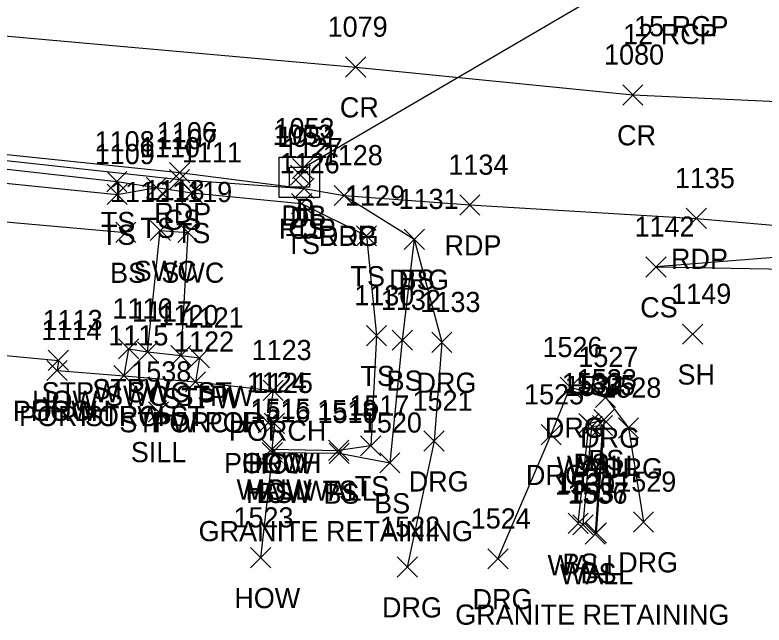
# Model space of a CAD drawing. Extents: x 1657482 to 1661439, y 647981 to 649041.
# Drawn here: x 1659731.7 to 1659806, y 648045.8 to 648106.3 of the extents above; entities that cross this region are included whole.
import ezdxf

# ---------------------------------------------------------------- set-up
doc = ezdxf.new("R2010")
doc.units = 0
for name, color, linetype in [('D_A', 7, 'Continuous'), ('D_C', 7, 'Continuous'), ('D_I', 7, 'Continuous'), ('D_TIC', 7, 'Continuous'), ('DCP', 7, 'Continuous'), ('DS', 7, 'Continuous'), ('L_A', 7, 'Continuous'), ('L_C', 7, 'Continuous'), ('L_I', 7, 'Continuous'), ('L_TIC', 7, 'Continuous'), ('LBC', 7, 'Continuous'), ('LBF', 7, 'Continuous'), ('LELB', 7, 'Continuous'), ('LW', 7, 'Continuous'), ('P_A', 7, 'Continuous'), ('P_I', 7, 'Continuous'), ('P_TIC', 7, 'Continuous'), ('PET', 7, 'Continuous'), ('PRC', 7, 'Continuous'), ('R_A', 7, 'Continuous'), ('R_I', 7, 'Continuous'), ('R_TIC', 7, 'Continuous'), ('RDG', 7, 'Continuous'), ('RSW', 7, 'Continuous')]:
    doc.layers.add(name, color=color, linetype=linetype)

msp = doc.modelspace()

# ---------------------------------------------------------------- linework, layer by layer
at = {"layer": 'D_TIC'}
for points in [[(1659759.227, 648090.081), (1659761.227, 648092.081)], [(1659761.227, 648090.081), (1659759.227, 648092.081)], [(1659759.037, 648089.421), (1659761.037, 648091.421)], [(1659761.037, 648089.421), (1659759.037, 648091.421)]]:
    msp.add_lwpolyline(points, dxfattribs=at)
at = {"layer": 'DCP'}
msp.add_lwpolyline([(1659796.66, 648112.405), (1659760.227, 648091.081)], dxfattribs=at)
at = {"layer": 'DS'}
for p, q in [((1659757.931, 648092.219), (1659761.931, 648092.219)), ((1659757.931, 648088.219), (1659757.931, 648092.219)), ((1659761.931, 648092.219), (1659761.931, 648088.219)), ((1659758.931, 648089.219), (1659758.931, 648091.219)), ((1659758.931, 648091.219), (1659760.931, 648091.219)), ((1659760.931, 648091.219), (1659760.931, 648089.219)), ((1659759.936, 648090.221), (1659759.936, 648090.221)), ((1659759.936, 648090.221), (1659759.936, 648090.221)), ((1659760.931, 648089.219), (1659758.931, 648089.219)), ((1659761.931, 648088.219), (1659757.931, 648088.219))]:
    msp.add_line(p, q, dxfattribs=at)
at = {"layer": 'L_TIC'}
for points in [[(1659747.036, 648088.997), (1659749.036, 648090.997)], [(1659749.036, 648088.997), (1659747.036, 648090.997)], [(1659740.823, 648088.778), (1659742.823, 648090.778)], [(1659742.823, 648088.778), (1659740.823, 648090.778)], [(1659740.847, 648087.516), (1659742.847, 648089.516)], [(1659742.847, 648087.516), (1659740.847, 648089.516)], [(1659744.757, 648088.198), (1659746.757, 648090.198)], [(1659746.757, 648088.198), (1659744.757, 648090.198)], [(1659744.757, 648088.198), (1659746.757, 648090.198)], [(1659746.757, 648088.198), (1659744.757, 648090.198)], [(1659748.269, 648087.683), (1659750.269, 648089.683)], [(1659750.269, 648087.683), (1659748.269, 648089.683)], [(1659759.398, 648088.114), (1659761.398, 648090.114)], [(1659761.398, 648088.114), (1659759.398, 648090.114)], [(1659759.143, 648086.603), (1659761.143, 648088.603)], [(1659761.143, 648086.603), (1659759.143, 648088.603)], [(1659741.71, 648083.749), (1659743.71, 648085.749)], [(1659743.71, 648083.749), (1659741.71, 648085.749)], [(1659765.578, 648083.403), (1659767.578, 648085.403)], [(1659767.578, 648083.403), (1659765.578, 648085.403)], [(1659770.317, 648083.067), (1659772.317, 648085.067)], [(1659772.317, 648083.067), (1659770.317, 648085.067)], [(1659794.275, 648080.325), (1659796.275, 648082.325)], [(1659796.275, 648080.325), (1659794.275, 648082.325)], [(1659766.572, 648073.522), (1659768.572, 648075.522)], [(1659768.572, 648073.522), (1659766.572, 648075.522)], [(1659797.923, 648073.665), (1659799.923, 648075.665)], [(1659799.923, 648073.665), (1659797.923, 648075.665)], [(1659769.125, 648073.06), (1659771.125, 648075.06)], [(1659771.125, 648073.06), (1659769.125, 648075.06)], [(1659741.995, 648072.212), (1659743.995, 648074.212)], [(1659743.995, 648072.212), (1659741.995, 648074.212)], [(1659743.871, 648071.903), (1659745.871, 648073.903)], [(1659745.871, 648071.903), (1659743.871, 648073.903)], [(1659747.168, 648071.552), (1659749.168, 648073.552)], [(1659749.168, 648071.552), (1659747.168, 648073.552)], [(1659749.005, 648071.317), (1659751.005, 648073.317)], [(1659751.005, 648071.317), (1659749.005, 648073.317)], [(1659735.024, 648071.064), (1659737.024, 648073.064)], [(1659737.024, 648071.064), (1659735.024, 648073.064)], [(1659734.891, 648070.068), (1659736.891, 648072.068)], [(1659736.891, 648070.068), (1659734.891, 648072.068)], [(1659734.891, 648070.068), (1659736.891, 648072.068)], [(1659736.891, 648070.068), (1659734.891, 648072.068)], [(1659741.54, 648069.547), (1659743.54, 648071.547)], [(1659743.54, 648069.547), (1659741.54, 648071.547)], [(1659741.54, 648069.547), (1659743.54, 648071.547)], [(1659743.54, 648069.547), (1659741.54, 648071.547)], [(1659748.618, 648068.931), (1659750.618, 648070.931)], [(1659750.618, 648068.931), (1659748.618, 648070.931)], [(1659748.618, 648068.931), (1659750.618, 648070.931)], [(1659750.618, 648068.931), (1659748.618, 648070.931)], [(1659756.314, 648068.091), (1659758.314, 648070.091)], [(1659758.314, 648068.091), (1659756.314, 648070.091)], [(1659744.948, 648065.971), (1659746.948, 648067.971)], [(1659746.948, 648065.971), (1659744.948, 648067.971)], [(1659755.822, 648064.888), (1659757.822, 648066.888)], [(1659757.822, 648064.888), (1659755.822, 648066.888)], [(1659755.822, 648064.888), (1659757.822, 648066.888)], [(1659757.822, 648064.888), (1659755.822, 648066.888)], [(1659756.441, 648064.828), (1659758.441, 648066.828)], [(1659758.441, 648064.828), (1659756.441, 648066.828)], [(1659787.642, 648064.811), (1659789.642, 648066.811)], [(1659789.642, 648064.811), (1659787.642, 648066.811)], [(1659787.932, 648064.531), (1659789.932, 648066.531)], [(1659789.932, 648064.531), (1659787.932, 648066.531)], [(1659788.977, 648064.607), (1659790.977, 648066.607)], [(1659790.977, 648064.607), (1659788.977, 648066.607)], [(1659789.124, 648065.193), (1659791.124, 648067.193)], [(1659791.124, 648065.193), (1659789.124, 648067.193)], [(1659756.202, 648062.257), (1659758.202, 648064.257)], [(1659758.202, 648062.257), (1659756.202, 648064.257)], [(1659756.202, 648062.257), (1659758.202, 648064.257)], [(1659758.202, 648062.257), (1659756.202, 648064.257)], [(1659765.992, 648062.591), (1659767.992, 648064.591)], [(1659767.992, 648062.591), (1659765.992, 648064.591)], [(1659756.239, 648061.928), (1659758.239, 648063.928)], [(1659758.239, 648061.928), (1659756.239, 648063.928)], [(1659756.239, 648061.928), (1659758.239, 648063.928)], [(1659758.239, 648061.928), (1659756.239, 648063.928)], [(1659762.81, 648062.143), (1659764.81, 648064.143)], [(1659764.81, 648062.143), (1659762.81, 648064.143)], [(1659762.81, 648062.143), (1659764.81, 648064.143)], [(1659764.81, 648062.143), (1659762.81, 648064.143)], [(1659762.867, 648061.857), (1659764.867, 648063.857)], [(1659764.867, 648061.857), (1659762.867, 648063.857)], [(1659767.897, 648060.904), (1659769.897, 648062.904)], [(1659769.897, 648060.904), (1659767.897, 648062.904)], [(1659767.897, 648060.904), (1659769.897, 648062.904)], [(1659769.897, 648060.904), (1659767.897, 648062.904)], [(1659786.559, 648054.92), (1659788.559, 648056.92)], [(1659788.559, 648054.92), (1659786.559, 648056.92)], [(1659787.047, 648054.764), (1659789.047, 648056.764)], [(1659789.047, 648054.764), (1659787.047, 648056.764)], [(1659788.253, 648053.862), (1659790.253, 648055.862)], [(1659790.253, 648053.862), (1659788.253, 648055.862)], [(1659788.356, 648053.962), (1659790.356, 648055.962)], [(1659790.356, 648053.962), (1659788.356, 648055.962)], [(1659755.082, 648051.504), (1659757.082, 648053.504)], [(1659757.082, 648051.504), (1659755.082, 648053.504)]]:
    msp.add_lwpolyline(points, dxfattribs=at)
at = {"layer": 'LBC'}
for points in [[(1659711.492, 648074.514), (1659713.585, 648074.237), (1659720.336, 648073.554), (1659736.024, 648072.064), (1659735.891, 648071.068)], [(1659756.822, 648065.888), (1659757.441, 648065.828), (1659757.202, 648063.257), (1659757.239, 648062.928), (1659756.082, 648052.504)]]:
    msp.add_lwpolyline(points, dxfattribs=at)
at = {"layer": 'LBF'}
for points in [[(1659742.54, 648070.547), (1659742.995, 648073.212), (1659744.871, 648072.903), (1659748.168, 648072.552), (1659750.005, 648072.317), (1659749.618, 648069.931)], [(1659735.891, 648071.068), (1659742.54, 648070.547), (1659749.618, 648069.931), (1659757.314, 648069.091), (1659756.822, 648065.888)]]:
    msp.add_lwpolyline(points, dxfattribs=at)
at = {"layer": 'LELB'}
for points in [[(1659698.339, 648094.515), (1659720.268, 648093.031), (1659748.036, 648089.997), (1659760.398, 648089.114)], [(1659698.344, 648093.996), (1659720.032, 648092.239), (1659741.823, 648089.778), (1659745.757, 648089.198), (1659749.269, 648088.683), (1659760.143, 648087.603), (1659766.578, 648084.403), (1659767.572, 648074.522), (1659766.992, 648063.591), (1659763.81, 648063.143)], [(1659701.625, 648092.494), (1659719.726, 648090.762), (1659741.847, 648088.516), (1659745.757, 648089.198)], [(1659719.21, 648086.816), (1659742.71, 648084.749)], [(1659771.317, 648084.067), (1659770.125, 648074.06), (1659768.897, 648061.904)], [(1659855.388, 648078.995), (1659852.388, 648081.027), (1659841.119, 648082.553), (1659821.287, 648083.368), (1659795.275, 648081.325), (1659823.275, 648080.854), (1659837.829, 648081.022), (1659847.593, 648080.286), (1659853.195, 648078.545)], [(1659787.559, 648055.92), (1659788.642, 648065.811), (1659790.124, 648066.193), (1659789.356, 648054.962)], [(1659757.239, 648062.928), (1659763.867, 648062.857), (1659768.897, 648061.904)]]:
    msp.add_lwpolyline(points, dxfattribs=at)
at = {"layer": 'LW'}
for points in [[(1659788.047, 648055.764), (1659788.932, 648065.531), (1659789.977, 648065.607), (1659789.253, 648054.862)], [(1659757.202, 648063.257), (1659763.81, 648063.143)]]:
    msp.add_lwpolyline(points, dxfattribs=at)
at = {"layer": 'P_TIC'}
for points in [[(1659764.503, 648100.141), (1659766.503, 648102.141)], [(1659766.503, 648100.141), (1659764.503, 648102.141)], [(1659791.988, 648097.376), (1659793.988, 648099.376)], [(1659793.988, 648097.376), (1659791.988, 648099.376)], [(1659747.043, 648089.675), (1659749.043, 648091.675)], [(1659749.043, 648089.675), (1659747.043, 648091.675)], [(1659759.398, 648088.114), (1659761.398, 648090.114)], [(1659761.398, 648088.114), (1659759.398, 648090.114)], [(1659763.367, 648087.405), (1659765.367, 648089.405)], [(1659765.367, 648087.405), (1659763.367, 648089.405)], [(1659775.821, 648086.465), (1659777.821, 648088.465)], [(1659777.821, 648086.465), (1659775.821, 648088.465)], [(1659798.28, 648085.136), (1659800.28, 648087.136)], [(1659800.28, 648085.136), (1659798.28, 648087.136)]]:
    msp.add_lwpolyline(points, dxfattribs=at)
at = {"layer": 'PET'}
msp.add_lwpolyline([(1659665.753, 648098.571), (1659698.631, 648095.118), (1659720.133, 648093.609), (1659748.043, 648090.675), (1659760.398, 648089.114), (1659764.367, 648088.405), (1659776.821, 648087.465), (1659799.28, 648086.136), (1659822.829, 648084.094)], dxfattribs=at)
at = {"layer": 'PRC'}
msp.add_lwpolyline([(1659666.144, 648110.534), (1659699.551, 648107.376), (1659729.526, 648104.331), (1659765.503, 648101.141), (1659792.988, 648098.376), (1659818.732, 648097.206), (1659849.225, 648095.841), (1659870.331, 648096.361), (1659894.597, 648099.456), (1659913.112, 648103.656), (1659935.294, 648110.794), (1659956.941, 648119.929), (1659978.865, 648130.6), (1660002.085, 648142.328), (1660031.609, 648158.263), (1660061.231, 648174.691), (1660097.076, 648195.768), (1660113.884, 648205.485), (1660151.727, 648227.302), (1660188.688, 648248.658)], dxfattribs=at)
at = {"layer": 'R_TIC'}
for points in [[(1659763.367, 648087.405), (1659765.367, 648089.405)], [(1659765.367, 648087.405), (1659763.367, 648089.405)], [(1659745.133, 648083.931), (1659747.133, 648085.931)], [(1659747.133, 648083.931), (1659745.133, 648085.931)], [(1659747.874, 648083.755), (1659749.874, 648085.755)], [(1659749.874, 648083.755), (1659747.874, 648085.755)], [(1659770.317, 648083.067), (1659772.317, 648085.067)], [(1659772.317, 648083.067), (1659770.317, 648085.067)], [(1659773.048, 648072.854), (1659775.048, 648074.854)], [(1659775.048, 648072.854), (1659773.048, 648074.854)], [(1659743.871, 648071.903), (1659745.871, 648073.903)], [(1659745.871, 648071.903), (1659743.871, 648073.903)], [(1659747.168, 648071.552), (1659749.168, 648073.552)], [(1659749.168, 648071.552), (1659747.168, 648073.552)], [(1659785.769, 648068.396), (1659787.769, 648070.396)], [(1659787.769, 648068.396), (1659785.769, 648070.396)], [(1659789.274, 648067.407), (1659791.274, 648069.407)], [(1659791.274, 648067.407), (1659789.274, 648069.407)], [(1659791.548, 648064.367), (1659793.548, 648066.367)], [(1659793.548, 648064.367), (1659791.548, 648066.367)], [(1659772.269, 648063.067), (1659774.269, 648065.067)], [(1659774.269, 648063.067), (1659772.269, 648065.067)], [(1659783.893, 648063.704), (1659785.893, 648065.704)], [(1659785.893, 648063.704), (1659783.893, 648065.704)], [(1659793.039, 648055.047), (1659795.039, 648057.047)], [(1659795.039, 648055.047), (1659793.039, 648057.047)], [(1659778.606, 648051.398), (1659780.606, 648053.398)], [(1659780.606, 648051.398), (1659778.606, 648053.398)], [(1659769.622, 648050.58), (1659771.622, 648052.58)], [(1659771.622, 648050.58), (1659769.622, 648052.58)]]:
    msp.add_lwpolyline(points, dxfattribs=at)
at = {"layer": 'RDG'}
for points in [[(1659764.367, 648088.405), (1659771.317, 648084.067), (1659774.048, 648073.854), (1659773.269, 648064.067), (1659770.622, 648051.58)], [(1659779.606, 648052.398), (1659784.893, 648064.704), (1659786.769, 648069.396), (1659790.274, 648068.407), (1659792.548, 648065.367), (1659794.039, 648056.047)]]:
    msp.add_lwpolyline(points, dxfattribs=at)
at = {"layer": 'RSW'}
msp.add_lwpolyline([(1659744.871, 648072.903), (1659746.133, 648084.931), (1659748.874, 648084.755), (1659748.168, 648072.552)], dxfattribs=at)

# ---------------------------------------------------------------- texts
at = {"layer": 'D_A'}
for s, p in [('P', (1659759.605, 648086.081)), ('DIB', (1659758.14, 648085.421)), ('DI', (1659758.991, 648085.221))]:
    msp.add_text(s, height=2, dxfattribs=at).set_placement(p)
at = {"layer": 'D_C'}
for s, p in [('15 RCP', (1659793.105, 648104.191)), ('12 RCP', (1659792.022, 648103.405))]:
    msp.add_text(s, height=2, dxfattribs=at).set_placement(p)
at = {"layer": 'D_I'}
for s, p in [('1052', (1659757.266, 648093.421)), ('1053', (1659757.456, 648094.081)), ('1051', (1659757.731, 648093.221))]:
    msp.add_text(s, height=2, dxfattribs=at).set_placement(p)
at = {"layer": 'L_A'}
for s, p in [('TS', (1659740.232, 648084.778)), ('CS', (1659746.477, 648084.997)), ('TS', (1659744.167, 648084.198)), ('TS', (1659744.167, 648084.198)), ('CS', (1659758.839, 648084.114)), ('TS', (1659740.257, 648083.516)), ('TS', (1659747.679, 648083.683)), ('TS', (1659758.552, 648082.603)), ('BS', (1659741.151, 648079.749)), ('TS', (1659764.988, 648079.403)), ('BS', (1659769.758, 648079.067)), ('CS', (1659793.716, 648076.325)), ('SH', (1659797.411, 648069.665)), ('TS', (1659765.982, 648069.522)), ('BS', (1659768.566, 648069.06)), ('STPW', (1659739.389, 648068.212)), ('STPW SWC ST', (1659734.359, 648067.903)), ('SWC STPW', (1659740.656, 648067.552)), ('HOW', (1659733.41, 648067.064)), ('STPW', (1659746.399, 648067.317)), ('PORCH', (1659731.513, 648066.068)), ('HOW', (1659733.277, 648066.068)), ('POR STPW ST', (1659732.123, 648065.547)), ('PORCH', (1659738.162, 648065.547)), ('STPW POR', (1659742.067, 648064.931)), ('PORCH', (1659745.24, 648064.931)), ('PORCH', (1659752.936, 648064.091)), ('SILL', (1659743.208, 648061.971)), ('PORCH', (1659752.444, 648060.888)), ('HOW', (1659754.208, 648060.888)), ('HOW', (1659754.827, 648060.828)), ('BS', (1659787.083, 648060.811)), ('BS', (1659788.565, 648061.193)), ('WALL', (1659785.42, 648060.531)), ('WALL', (1659786.465, 648060.607)), ('TS', (1659765.402, 648058.591)), ('WALL', (1659753.69, 648058.257)), ('HOW', (1659754.588, 648058.257)), ('HOW', (1659754.625, 648057.928)), ('BS', (1659755.68, 648057.928)), ('WALL', (1659760.298, 648058.143)), ('TS', (1659762.22, 648058.143)), ('BS', (1659762.308, 648057.857)), ('BS', (1659767.338, 648056.904)), ('BS', (1659767.338, 648056.904)), ('WALL', (1659784.535, 648050.764)), ('BS', (1659786, 648050.92)), ('WALL', (1659785.741, 648049.862)), ('BS', (1659787.797, 648049.962)), ('HOW', (1659753.468, 648047.504))]:
    msp.add_text(s, height=2, dxfattribs=at).set_placement(p)
at = {"layer": 'L_C'}
for p in [(1659749.929, 648054.143), (1659775.371, 648045.862)]:
    msp.add_text('GRANITE RETAINING', height=2, dxfattribs=at).set_placement(p)
at = {"layer": 'L_I'}
for s, p in [('1108', (1659739.618, 648092.778)), ('1107', (1659745.832, 648092.997)), ('1110', (1659744.112, 648092.198)), ('1110', (1659744.112, 648092.198)), ('1127', (1659758.272, 648092.114)), ('1109', (1659739.635, 648091.516)), ('1111', (1659748.278, 648091.683)), ('1126', (1659757.962, 648090.603)), ('1112', (1659741.151, 648087.749)), ('1129', (1659764.445, 648087.403)), ('1131', (1659769.758, 648087.067)), ('1142', (1659793.149, 648084.325)), ('1130', (1659765.36, 648077.522)), ('1149', (1659796.789, 648077.665)), ('1132', (1659768, 648077.06)), ('1116', (1659741.382, 648076.212)), ('1117', (1659743.312, 648075.903)), ('1113', (1659734.465, 648075.064)), ('1120', (1659745.956, 648075.552)), ('1121', (1659748.446, 648075.317)), ('1114', (1659734.333, 648074.068)), ('1114', (1659734.333, 648074.068)), ('1115', (1659740.981, 648073.547)), ('1115', (1659740.981, 648073.547)), ('1122', (1659747.493, 648072.931)), ('1122', (1659747.493, 648072.931)), ('1123', (1659755.188, 648072.091)), ('1538', (1659743.255, 648069.971)), ('1533', (1659787.431, 648069.193)), ('1124', (1659754.696, 648068.888)), ('1124', (1659754.696, 648068.888)), ('1125', (1659755.315, 648068.828)), ('1532', (1659785.949, 648068.811)), ('1534', (1659786.239, 648068.531)), ('1535', (1659787.284, 648068.607)), ('1516', (1659755.059, 648065.928)), ('1516', (1659755.059, 648065.928)), ('1515', (1659755.076, 648066.257)), ('1515', (1659755.076, 648066.257)), ('1518', (1659761.685, 648066.143)), ('1518', (1659761.685, 648066.143)), ('1517', (1659764.867, 648066.591)), ('1519', (1659761.734, 648065.857)), ('1520', (1659766.118, 648064.904)), ('1520', (1659766.118, 648064.904)), ('1530', (1659785.268, 648058.764)), ('1531', (1659785.433, 648058.92)), ('1536', (1659786.505, 648057.862)), ('1537', (1659786.663, 648057.962)), ('1523', (1659753.389, 648055.504))]:
    msp.add_text(s, height=2, dxfattribs=at).set_placement(p)
at = {"layer": 'P_A'}
for s, p in [('CR', (1659763.936, 648096.141)), ('CR', (1659791.421, 648093.376)), ('RDP', (1659745.531, 648085.675)), ('RDP', (1659757.886, 648084.114)), ('RDP', (1659761.855, 648083.405)), ('RDP', (1659774.309, 648082.465)), ('RDP', (1659796.768, 648081.136))]:
    msp.add_text(s, height=2, dxfattribs=at).set_placement(p)
at = {"layer": 'P_I'}
for s, p in [('1079', (1659762.723, 648104.141)), ('1080', (1659790.13, 648101.376)), ('1106', (1659745.784, 648093.675)), ('1127', (1659758.272, 648092.114)), ('1128', (1659762.241, 648091.405)), ('1134', (1659774.695, 648090.465)), ('1135', (1659797.154, 648089.136))]:
    msp.add_text(s, height=2, dxfattribs=at).set_placement(p)
at = {"layer": 'R_A'}
for s, p in [('DRG', (1659761.855, 648083.405)), ('SWC', (1659743.495, 648079.931)), ('SWC', (1659746.236, 648079.755)), ('DRG', (1659768.805, 648079.067)), ('DRG', (1659771.536, 648068.854)), ('STPW SWC ST', (1659734.359, 648067.903)), ('SWC STPW', (1659740.656, 648067.552)), ('DRG', (1659784.257, 648064.396)), ('DRG', (1659787.762, 648063.407)), ('DRG', (1659790.036, 648060.367)), ('DRG', (1659782.382, 648059.704)), ('DRG', (1659770.757, 648059.067)), ('DRG', (1659791.527, 648051.047)), ('DRG', (1659777.094, 648047.398)), ('DRG', (1659768.11, 648046.58))]:
    msp.add_text(s, height=2, dxfattribs=at).set_placement(p)
at = {"layer": 'R_I'}
for s, p in [('1128', (1659762.241, 648091.405)), ('1118', (1659744.574, 648087.931)), ('1119', (1659747.307, 648087.755)), ('1131', (1659769.758, 648087.067)), ('1133', (1659771.923, 648076.854)), ('1117', (1659743.312, 648075.903)), ('1120', (1659745.956, 648075.552)), ('1526', (1659784.021, 648072.396)), ('1527', (1659787.581, 648071.407)), ('1528', (1659789.855, 648068.367)), ('1525', (1659782.201, 648067.704)), ('1521', (1659771.143, 648067.067)), ('1529', (1659791.338, 648059.047)), ('1524', (1659776.913, 648055.398)), ('1522', (1659767.929, 648054.58))]:
    msp.add_text(s, height=2, dxfattribs=at).set_placement(p)

doc.saveas('drawing.dxf')
